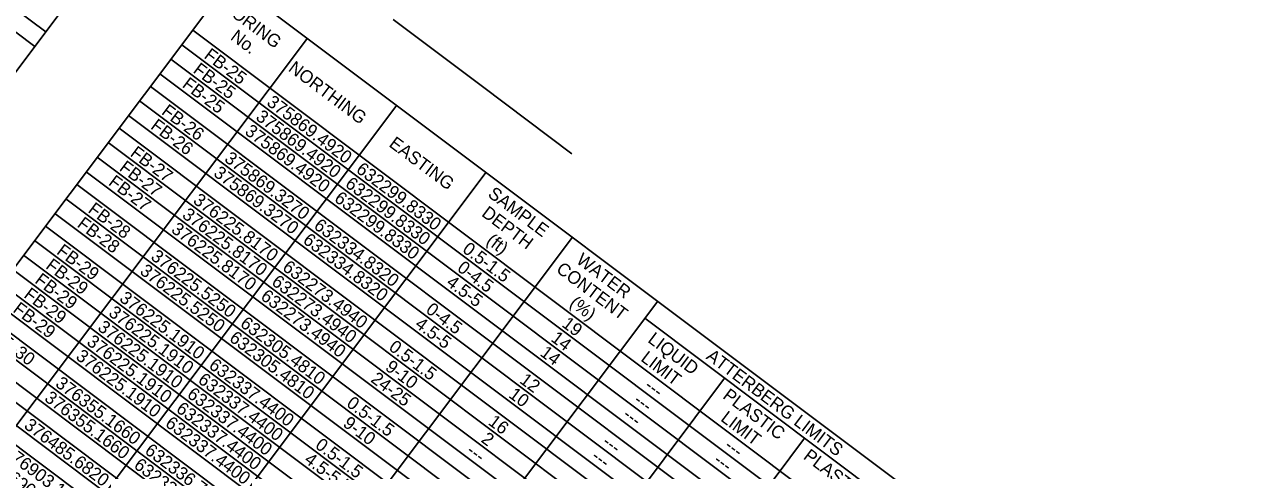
# Model space of a CAD drawing. Extents: x 627484.2 to 627517.5, y 367968.7 to 367996.9.
# Drawn here: x 627492.24 to 627497.5, y 367990.56 to 367992.47 of the extents above; entities that cross this region are included whole.
import ezdxf

# ---------------------------------------------------------------- set-up
doc = ezdxf.new("R2010")
doc.units = 0
doc.layers.add('Default', color=7, linetype='Continuous')
doc.layers.add('R_Survey Control', color=7, linetype='Continuous')

msp = doc.modelspace()

# ---------------------------------------------------------------- linework, layer by layer
at = {"layer": 'Default'}
for p, q in [((627487.0846, 367996.3788), (627492.3275, 367992.4419)), ((627487.0378, 367996.3164), (627492.2807, 367992.3795)), ((627490.9576, 367990.6175), (627492.7198, 367992.9642)), ((627491.2374, 367990.1574), (627493.1196, 367992.664)), ((627493.1196, 367992.664), (627498.3625, 367988.727)), ((627491.5219, 367989.8462), (627493.451, 367992.4152)), ((627492.9586, 367992.4496), (627498.2015, 367988.5126)), ((627492.9118, 367992.3872), (627498.1547, 367988.4503)), ((627492.8649, 367992.3248), (627498.1078, 367988.3879)), ((627492.8181, 367992.2625), (627498.061, 367988.3255)), ((627492.7771, 367992.2079), (627498.02, 367988.2709)), ((627490.4128, 367987.5698), (627493.8348, 367992.127)), ((627492.7303, 367992.1455), (627497.9732, 367988.2086)), ((627492.6834, 367992.0832), (627497.9263, 367988.1462)), ((627492.6425, 367992.0286), (627497.8854, 367988.0916)), ((627492.5956, 367991.9662), (627497.8385, 367988.0293)), ((627492.5488, 367991.9038), (627497.7917, 367987.9669)), ((627490.7966, 367987.2816), (627494.2186, 367991.8387)), ((627492.5019, 367991.8415), (627497.7449, 367987.9045)), ((627492.461, 367991.7869), (627497.7039, 367987.8499)), ((627492.4141, 367991.7245), (627497.657, 367987.7876)), ((627492.3673, 367991.6621), (627497.6102, 367987.7252)), ((627492.3263, 367991.6076), (627497.5692, 367987.6706)), ((627492.2795, 367991.5452), (627497.5224, 367987.6082)), ((627492.6599, 367988.9917), (627494.589, 367991.5606)), ((627492.2326, 367991.4828), (627497.4755, 367987.5459)), ((627492.1858, 367991.4204), (627497.4287, 367987.4835)), ((627492.139, 367991.3581), (627497.3819, 367987.4211)), ((627492.0921, 367991.2957), (627497.335, 367987.3587)), ((627493.0263, 367988.7165), (627494.9554, 367991.2855)), ((627492.0511, 367991.2411), (627497.2941, 367987.3042)), ((627494.8998, 367991.2114), (627496.0537, 367990.3449)), ((627492.0043, 367991.1787), (627497.2472, 367987.2418)), ((627491.9575, 367991.1164), (627497.2004, 367987.1794)), ((627491.9165, 367991.0618), (627497.1594, 367987.1248)), ((627491.8697, 367990.9994), (627497.1126, 367987.0625)), ((627491.8287, 367990.9448), (627497.0716, 367987.0079)), ((627494.5052, 367989.9714), (627495.2428, 367990.9538)), ((627494.8482, 367989.7138), (627495.5859, 367990.6962))]:
    msp.add_line(p, q, dxfattribs=at)
at = {"layer": 'R_Survey Control'}
for p, q in [((627493.8189, 367992.4954), (627494.2027, 367992.2071)), ((627494.2027, 367992.2071), (627494.5865, 367991.9189))]:
    msp.add_line(p, q, dxfattribs=at)

# ---------------------------------------------------------------- texts
at = {"layer": 'Default'}
for s, p in [('BORING', (627493.0814, 367992.5422)), ('No.', (627493.117, 367992.4123)), ('FB-25', (627493.0035, 367992.3327)), ('FB-25', (627492.9566, 367992.2704)), ('NORTHING', (627493.3655, 367992.2773)), ('FB-25', (627492.9098, 367992.208)), ('375869.4920', (627493.2725, 367992.1307)), ('FB-26', (627492.8211, 367992.0917)), ('375869.4920', (627493.2257, 367992.0683)), ('FB-26', (627492.7742, 367992.0293)), ('375869.4920', (627493.1788, 367992.006)), ('EASTING', (627493.7975, 367991.9529)), ('FB-27', (627492.6866, 367991.9122)), ('FB-27', (627492.6398, 367991.8499)), ('375869.3270', (627493.091, 367991.889)), ('375869.3270', (627493.0442, 367991.8266)), ('632299.8330', (627493.6563, 367991.8425)), ('FB-27', (627492.593, 367991.7875)), ('632299.8330', (627493.6095, 367991.7801)), ('376225.8170', (627492.9564, 367991.7097)), ('632299.8330', (627493.5627, 367991.7177)), ('SAMPLE', (627494.2223, 367991.7371)), ('FB-28', (627492.5055, 367991.6702)), ('376225.8170', (627492.9095, 367991.6473)), ('DEPTH', (627494.1953, 367991.6542)), ('FB-28', (627492.4587, 367991.6079)), ('632334.8320', (627493.4749, 367991.6008)), ('376225.8170', (627492.8627, 367991.5849)), ('632334.8320', (627493.428, 367991.5384)), ('(ft)', (627494.2152, 367991.5361)), ('FB-29', (627492.3704, 367991.4913)), ('0.5-1.5', (627494.113, 367991.4996)), ('FB-29', (627492.3236, 367991.4289)), ('376225.5250', (627492.7749, 367991.468)), ('WATER', (627494.6015, 367991.4523)), ('376225.5250', (627492.728, 367991.4056)), ('632273.4940', (627493.3402, 367991.4215)), ('0-4.5', (627494.0905, 367991.4189)), ('CONTENT', (627494.5155, 367991.4138)), ('FB-29', (627492.2767, 367991.3665)), ('632273.4940', (627493.2934, 367991.3591)), ('4.5-5', (627494.0436, 367991.3566)), ('FB-29', (627492.2299, 367991.3042)), ('376225.1910', (627492.6402, 367991.2887)), ('632273.4940', (627493.2465, 367991.2967)), ('FB-29', (627492.1831, 367991.2418)), ('376225.1910', (627492.5934, 367991.2263)), ('0-4.5', (627493.9558, 367991.2396)), ('(%)', (627494.5727, 367991.2676)), ('632305.4810', (627493.1587, 367991.1798)), ('4.5-5', (627493.909, 367991.1772)), ('19', (627494.5401, 367991.1788)), ('FB-30', (627492.095, 367991.125)), ('376225.1910', (627492.5465, 367991.1639)), ('632305.4810', (627493.1119, 367991.1174)), ('LIQUID', (627494.9089, 367991.112)), ('376225.1910', (627492.4997, 367991.1016)), ('0.5-1.5', (627493.7968, 367991.0786)), ('14', (627494.493, 367991.1167)), ('376225.1910', (627492.4529, 367991.0392)), ('14', (627494.4462, 367991.0543)), ('LIMIT', (627494.8791, 367991.0312)), ('ATTERBERG LIMITS', (627495.1595, 367991.0399)), ('632337.4400', (627493.0241, 367991.0005)), ('9-10', (627493.7815, 367990.9926)), ('376355.1660', (627492.3651, 367990.9222)), ('632337.4400', (627492.9772, 367990.9381)), ('24-25', (627493.7194, 367990.9417)), ('12', (627494.3586, 367990.9372)), ('376355.1660', (627492.3182, 367990.8599)), ('632337.4400', (627492.9304, 367990.8757)), ('10', (627494.3116, 367990.8749)), ('---', (627494.8948, 367990.9125)), ('PLASTIC', (627495.2307, 367990.8704)), ('632337.4400', (627492.8835, 367990.8133)), ('0.5-1.5', (627493.6153, 367990.8369)), ('---', (627494.848, 367990.8501)), ('632337.4400', (627492.8367, 367990.751)), ('9-10', (627493.6, 367990.7509)), ('16', (627494.2239, 367990.7579)), ('---', (627494.8011, 367990.7878)), ('LIMIT', (627495.2221, 367990.7736)), ('376485.6820', (627492.2304, 367990.7429)), ('0.5-1.5', (627493.4807, 367990.6576)), ('2', (627494.1934, 367990.6833)), ('---', (627494.7133, 367990.6708)), ('376903.1860', (627492.1426, 367990.626)), ('632336.7860', (627492.7489, 367990.634)), ('4.5-5.5', (627493.4338, 367990.5952)), ('---', (627494.1302, 367990.6331)), ('---', (627494.6665, 367990.6084)), ('---', (627495.2379, 367990.6549)), ('PLASTICITY', (627495.5769, 367990.6104)), ('376903.1860', (627492.0958, 367990.5636)), ('632336.7860', (627492.7021, 367990.5716)), ('---', (627495.191, 367990.5925))]:
    msp.add_text(s, height=0.055, rotation=323.0968, dxfattribs=at).set_placement(p)

doc.saveas('drawing.dxf')
